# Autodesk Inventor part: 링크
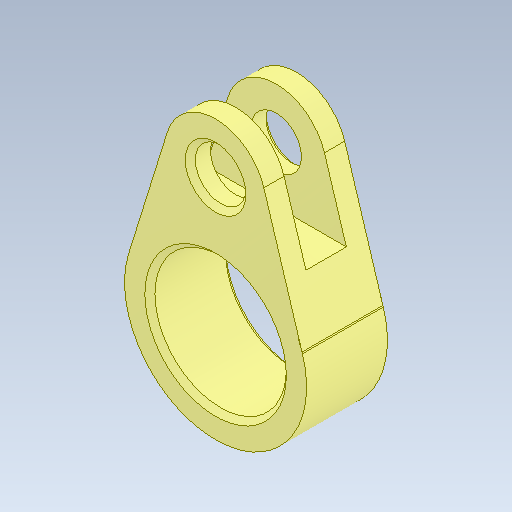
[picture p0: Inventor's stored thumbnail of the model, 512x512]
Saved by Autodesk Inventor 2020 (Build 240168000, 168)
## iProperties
Created: 2024-08
Part Number: 링크
Material: 강철, 연강
Document SubType Name: Modeling
Designer: oem
Density: 7.85 g/cm^3
Appearance: 기본값
Author: jhkim
Sending System: Autodesk Inventor 2025
Preprocessor: ST-DEVELOPER v20
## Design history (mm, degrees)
node "링크1"
node "솔리드2"
node "솔리드1"
